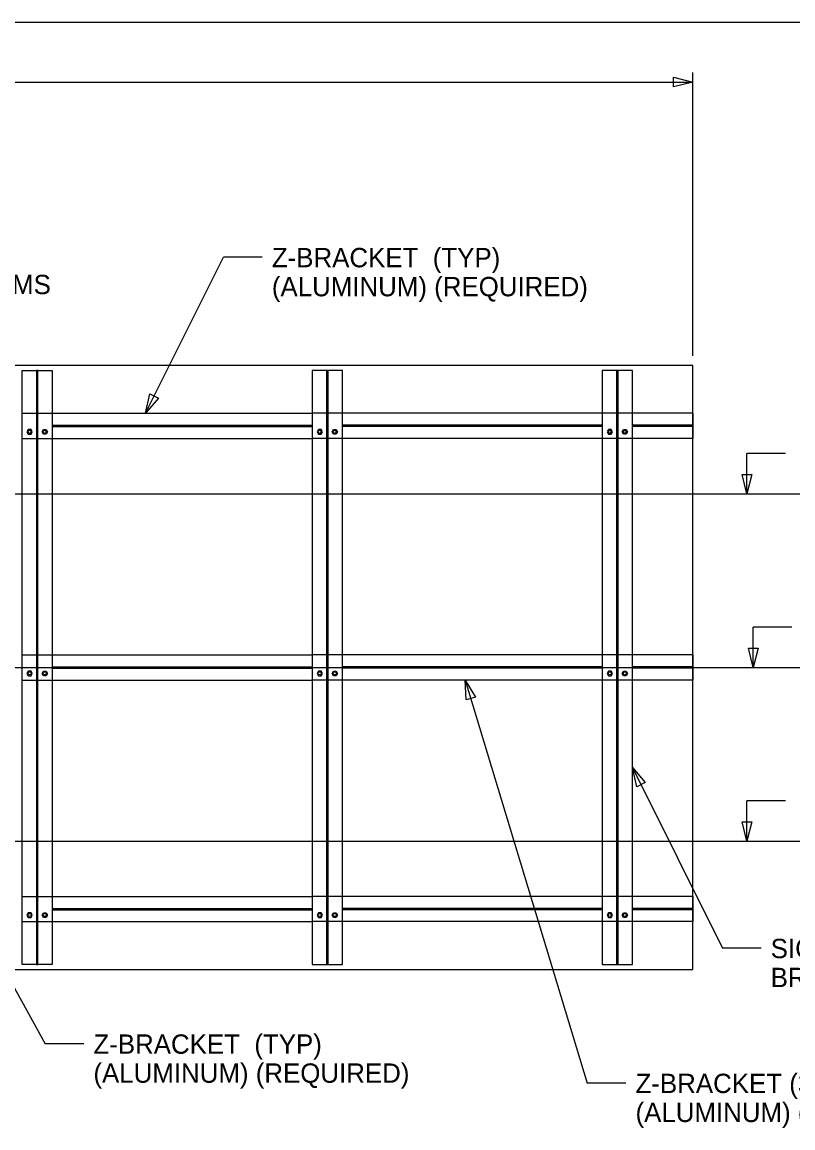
# Model space of a CAD drawing. Extents: x 3831399 to 3833095, y 499014 to 500202.
# Drawn here: x 3832677.7 to 3832797.3, y 499421.4 to 499593 of the extents above; entities that cross this region are included whole.
import ezdxf

# ---------------------------------------------------------------- set-up
doc = ezdxf.new("R2010")
doc.units = 0
for name, color, linetype in [('0-ANCHOR', 7, 'Continuous'), ('2', 7, 'Continuous'), ('CNTR', 7, 'Continuous'), ('DIM TXT', 7, 'Continuous'), ('sign', 7, 'Continuous'), ('structure', 7, 'Continuous')]:
    doc.layers.add(name, color=color, linetype=linetype)

msp = doc.modelspace()

# ---------------------------------------------------------------- linework, layer by layer
at = {"layer": '0-ANCHOR'}
for p, q in [((3832678.64, 499529.81), (3832678.43, 499529.45)), ((3832678.43, 499529.45), (3832678.64, 499529.09)), ((3832679.06, 499529.81), (3832678.64, 499529.81)), ((3832678.64, 499529.09), (3832679.06, 499529.09)), ((3832679.26, 499529.45), (3832679.06, 499529.81)), ((3832679.06, 499529.09), (3832679.26, 499529.45)), ((3832680.77, 499529.45), (3832680.98, 499529.81)), ((3832680.98, 499529.09), (3832680.77, 499529.45)), ((3832680.98, 499529.81), (3832681.39, 499529.81)), ((3832681.39, 499529.09), (3832680.98, 499529.09)), ((3832681.39, 499529.81), (3832681.6, 499529.45)), ((3832681.6, 499529.45), (3832681.39, 499529.09)), ((3832723.64, 499529.81), (3832723.43, 499529.45)), ((3832723.43, 499529.45), (3832723.64, 499529.09)), ((3832724.05, 499529.81), (3832723.64, 499529.81)), ((3832723.64, 499529.09), (3832724.05, 499529.09)), ((3832724.26, 499529.45), (3832724.05, 499529.81)), ((3832724.05, 499529.09), (3832724.26, 499529.45)), ((3832725.77, 499529.45), (3832725.98, 499529.81)), ((3832725.98, 499529.09), (3832725.77, 499529.45)), ((3832725.98, 499529.81), (3832726.39, 499529.81)), ((3832726.39, 499529.09), (3832725.98, 499529.09)), ((3832726.39, 499529.81), (3832726.6, 499529.45)), ((3832726.6, 499529.45), (3832726.39, 499529.09)), ((3832768.64, 499529.81), (3832768.43, 499529.45)), ((3832768.43, 499529.45), (3832768.64, 499529.09)), ((3832769.05, 499529.81), (3832768.64, 499529.81)), ((3832768.64, 499529.09), (3832769.05, 499529.09)), ((3832769.26, 499529.45), (3832769.05, 499529.81)), ((3832769.05, 499529.09), (3832769.26, 499529.45)), ((3832770.77, 499529.45), (3832770.97, 499529.81)), ((3832770.97, 499529.09), (3832770.77, 499529.45)), ((3832770.97, 499529.81), (3832771.39, 499529.81)), ((3832771.39, 499529.09), (3832770.97, 499529.09)), ((3832771.39, 499529.81), (3832771.6, 499529.45)), ((3832771.6, 499529.45), (3832771.39, 499529.09)), ((3832678.64, 499492.31), (3832678.43, 499491.95)), ((3832678.43, 499491.95), (3832678.64, 499491.59)), ((3832679.06, 499492.31), (3832678.64, 499492.31)), ((3832678.64, 499491.59), (3832679.06, 499491.59)), ((3832679.26, 499491.95), (3832679.06, 499492.31)), ((3832679.06, 499491.59), (3832679.26, 499491.95)), ((3832680.77, 499491.95), (3832680.98, 499492.31)), ((3832680.98, 499491.59), (3832680.77, 499491.95)), ((3832680.98, 499492.31), (3832681.39, 499492.31)), ((3832681.39, 499491.59), (3832680.98, 499491.59)), ((3832681.39, 499492.31), (3832681.6, 499491.95)), ((3832681.6, 499491.95), (3832681.39, 499491.59)), ((3832723.64, 499492.31), (3832723.43, 499491.95)), ((3832723.43, 499491.95), (3832723.64, 499491.59)), ((3832724.05, 499492.31), (3832723.64, 499492.31)), ((3832723.64, 499491.59), (3832724.05, 499491.59)), ((3832724.26, 499491.95), (3832724.05, 499492.31)), ((3832724.05, 499491.59), (3832724.26, 499491.95)), ((3832725.77, 499491.95), (3832725.98, 499492.31)), ((3832725.98, 499491.59), (3832725.77, 499491.95)), ((3832725.98, 499492.31), (3832726.39, 499492.31)), ((3832726.39, 499491.59), (3832725.98, 499491.59)), ((3832726.39, 499492.31), (3832726.6, 499491.95)), ((3832726.6, 499491.95), (3832726.39, 499491.59)), ((3832768.64, 499492.31), (3832768.43, 499491.95)), ((3832768.43, 499491.95), (3832768.64, 499491.59)), ((3832769.05, 499492.31), (3832768.64, 499492.31)), ((3832768.64, 499491.59), (3832769.05, 499491.59)), ((3832769.26, 499491.95), (3832769.05, 499492.31)), ((3832769.05, 499491.59), (3832769.26, 499491.95)), ((3832770.77, 499491.95), (3832770.97, 499492.31)), ((3832770.97, 499491.59), (3832770.77, 499491.95)), ((3832770.97, 499492.31), (3832771.39, 499492.31)), ((3832771.39, 499491.59), (3832770.97, 499491.59)), ((3832771.39, 499492.31), (3832771.6, 499491.95)), ((3832771.6, 499491.95), (3832771.39, 499491.59)), ((3832678.64, 499454.81), (3832678.43, 499454.45)), ((3832678.43, 499454.45), (3832678.64, 499454.09)), ((3832679.06, 499454.81), (3832678.64, 499454.81)), ((3832678.64, 499454.09), (3832679.06, 499454.09)), ((3832679.26, 499454.45), (3832679.06, 499454.81)), ((3832679.06, 499454.09), (3832679.26, 499454.45)), ((3832680.77, 499454.45), (3832680.98, 499454.81)), ((3832680.98, 499454.09), (3832680.77, 499454.45)), ((3832680.98, 499454.81), (3832681.39, 499454.81)), ((3832681.39, 499454.09), (3832680.98, 499454.09)), ((3832681.39, 499454.81), (3832681.6, 499454.45)), ((3832681.6, 499454.45), (3832681.39, 499454.09)), ((3832723.64, 499454.81), (3832723.43, 499454.45)), ((3832723.43, 499454.45), (3832723.64, 499454.09)), ((3832724.05, 499454.81), (3832723.64, 499454.81)), ((3832723.64, 499454.09), (3832724.05, 499454.09)), ((3832724.26, 499454.45), (3832724.05, 499454.81)), ((3832724.05, 499454.09), (3832724.26, 499454.45)), ((3832725.77, 499454.45), (3832725.98, 499454.81)), ((3832725.98, 499454.09), (3832725.77, 499454.45)), ((3832725.98, 499454.81), (3832726.39, 499454.81)), ((3832726.39, 499454.09), (3832725.98, 499454.09)), ((3832726.39, 499454.81), (3832726.6, 499454.45)), ((3832726.6, 499454.45), (3832726.39, 499454.09)), ((3832768.64, 499454.81), (3832768.43, 499454.45)), ((3832768.43, 499454.45), (3832768.64, 499454.09)), ((3832769.05, 499454.81), (3832768.64, 499454.81)), ((3832768.64, 499454.09), (3832769.05, 499454.09)), ((3832769.26, 499454.45), (3832769.05, 499454.81)), ((3832769.05, 499454.09), (3832769.26, 499454.45)), ((3832770.77, 499454.45), (3832770.97, 499454.81)), ((3832770.97, 499454.09), (3832770.77, 499454.45)), ((3832770.97, 499454.81), (3832771.39, 499454.81)), ((3832771.39, 499454.09), (3832770.97, 499454.09)), ((3832771.39, 499454.81), (3832771.6, 499454.45)), ((3832771.6, 499454.45), (3832771.39, 499454.09))]:
    msp.add_line(p, q, dxfattribs=at)
for centre in [(3832678.85, 499529.45), (3832681.18, 499529.45), (3832723.85, 499529.45), (3832726.18, 499529.45), (3832768.85, 499529.45), (3832771.18, 499529.45), (3832678.85, 499491.95), (3832681.18, 499491.95), (3832723.85, 499491.95), (3832726.18, 499491.95), (3832768.85, 499491.95), (3832771.18, 499491.95), (3832678.85, 499454.45), (3832681.18, 499454.45), (3832723.85, 499454.45), (3832726.18, 499454.45), (3832768.85, 499454.45), (3832771.18, 499454.45)]:
    msp.add_circle(centre, 0.244, dxfattribs=at)
at = {"layer": '2'}
msp.add_line((3832280.16, 499593.03), (3833066.16, 499593.03), dxfattribs=at)
at = {"layer": 'CNTR'}
for p, q in [((3832528.61, 499519.83), (3832815.35, 499519.83)), ((3832528.61, 499492.88), (3832829.18, 499492.88)), ((3832528.61, 499465.92), (3832815.12, 499465.92))]:
    msp.add_line(p, q, dxfattribs=at)
at = {"layer": 'DIM TXT'}
for p, q in [((3832533.3, 499583.72), (3832781.73, 499583.72)), ((3832781.73, 499541.25), (3832781.73, 499585.22)), ((3832696.82, 499532.33), (3832708.92, 499556.54)), ((3832714.92, 499556.54), (3832708.92, 499556.54)), ((3832790.12, 499519.83), (3832790.12, 499526.08)), ((3832796.12, 499526.08), (3832790.12, 499526.08)), ((3832791.1, 499492.88), (3832791.1, 499499.13)), ((3832797.1, 499499.13), (3832791.1, 499499.13)), ((3832746.43, 499490.92), (3832765.34, 499428.38)), ((3832772.35, 499477.37), (3832786.31, 499449.32)), ((3832790.12, 499465.92), (3832790.12, 499472.17)), ((3832796.12, 499472.17), (3832790.12, 499472.17)), ((3832670.7, 499453.43), (3832681.24, 499434.48)), ((3832792.31, 499449.32), (3832786.31, 499449.32)), ((3832687.24, 499434.48), (3832681.24, 499434.48)), ((3832771.34, 499428.38), (3832765.34, 499428.38))]:
    msp.add_line(p, q, dxfattribs=at)
for points in [[(3832778.73, 499584.47), (3832781.73, 499583.72), (3832778.73, 499582.97)], [(3832698.83, 499534.68), (3832696.82, 499532.33), (3832697.49, 499535.35)], [(3832790.87, 499522.83), (3832790.12, 499519.83), (3832789.37, 499522.83)], [(3832791.85, 499495.88), (3832791.1, 499492.88), (3832790.35, 499495.88)], [(3832746.58, 499487.84), (3832746.43, 499490.92), (3832748.01, 499488.27)], [(3832773.02, 499474.35), (3832772.35, 499477.37), (3832774.36, 499475.01)], [(3832790.87, 499468.92), (3832790.12, 499465.92), (3832789.37, 499468.92)]]:
    msp.add_lwpolyline(points, close=True, dxfattribs=at)
at = {"layer": 'sign'}
for p, q in [((3832781.73, 499539.75), (3832533.3, 499539.75)), ((3832781.73, 499446), (3832781.73, 499539.75)), ((3832677.68, 499532.33), (3832682.36, 499532.33)), ((3832682.36, 499532.33), (3832722.68, 499532.33)), ((3832727.36, 499532.33), (3832722.68, 499532.33)), ((3832767.67, 499532.33), (3832727.36, 499532.33)), ((3832772.35, 499532.33), (3832767.67, 499532.33)), ((3832781.73, 499532.33), (3832772.35, 499532.33)), ((3832781.73, 499532.33), (3832781.73, 499528.42)), ((3832682.36, 499530.47), (3832722.68, 499530.47)), ((3832767.67, 499530.47), (3832727.36, 499530.47)), ((3832781.73, 499530.47), (3832772.35, 499530.47)), ((3832682.36, 499530.28), (3832722.68, 499530.28)), ((3832767.67, 499530.28), (3832727.36, 499530.28)), ((3832781.73, 499530.28), (3832772.35, 499530.28)), ((3832677.68, 499528.42), (3832682.36, 499528.42)), ((3832682.36, 499528.42), (3832722.68, 499528.42)), ((3832727.36, 499528.42), (3832722.68, 499528.42)), ((3832767.67, 499528.42), (3832727.36, 499528.42)), ((3832772.35, 499528.42), (3832767.67, 499528.42)), ((3832781.73, 499528.42), (3832772.35, 499528.42)), ((3832677.68, 499494.83), (3832682.36, 499494.83)), ((3832682.36, 499494.83), (3832722.68, 499494.83)), ((3832727.36, 499494.83), (3832722.68, 499494.83)), ((3832767.67, 499494.83), (3832727.36, 499494.83)), ((3832772.35, 499494.83), (3832767.67, 499494.83)), ((3832781.73, 499494.83), (3832772.35, 499494.83)), ((3832781.73, 499494.83), (3832781.73, 499490.92)), ((3832682.36, 499492.97), (3832722.68, 499492.97)), ((3832682.36, 499492.78), (3832722.68, 499492.78)), ((3832767.67, 499492.97), (3832727.36, 499492.97)), ((3832767.67, 499492.78), (3832727.36, 499492.78)), ((3832781.73, 499492.97), (3832772.35, 499492.97)), ((3832781.73, 499492.78), (3832772.35, 499492.78)), ((3832677.68, 499490.92), (3832682.36, 499490.92)), ((3832682.36, 499490.92), (3832722.68, 499490.92)), ((3832727.36, 499490.92), (3832722.68, 499490.92)), ((3832767.67, 499490.92), (3832727.36, 499490.92)), ((3832772.35, 499490.92), (3832767.67, 499490.92)), ((3832781.73, 499490.92), (3832772.35, 499490.92)), ((3832677.68, 499457.33), (3832682.36, 499457.33)), ((3832682.36, 499457.33), (3832722.68, 499457.33)), ((3832727.36, 499457.33), (3832722.68, 499457.33)), ((3832767.67, 499457.33), (3832727.36, 499457.33)), ((3832772.35, 499457.33), (3832767.67, 499457.33)), ((3832781.73, 499457.33), (3832772.35, 499457.33)), ((3832781.73, 499457.33), (3832781.73, 499453.43)), ((3832682.36, 499455.48), (3832722.68, 499455.48)), ((3832682.36, 499455.28), (3832722.68, 499455.28)), ((3832767.67, 499455.48), (3832727.36, 499455.48)), ((3832767.67, 499455.28), (3832727.36, 499455.28)), ((3832781.73, 499455.48), (3832772.35, 499455.48)), ((3832781.73, 499455.28), (3832772.35, 499455.28)), ((3832677.68, 499453.43), (3832682.36, 499453.43)), ((3832682.36, 499453.43), (3832722.68, 499453.43)), ((3832727.36, 499453.43), (3832722.68, 499453.43)), ((3832767.67, 499453.43), (3832727.36, 499453.43)), ((3832772.35, 499453.43), (3832767.67, 499453.43)), ((3832781.73, 499453.43), (3832772.35, 499453.43)), ((3832533.3, 499446), (3832781.73, 499446))]:
    msp.add_line(p, q, dxfattribs=at)
at = {"layer": 'structure'}
for p, q in [((3832677.68, 499538.97), (3832682.36, 499538.97)), ((3832677.68, 499446.78), (3832677.68, 499538.97)), ((3832680.11, 499538.97), (3832679.93, 499538.97)), ((3832679.93, 499538.97), (3832679.93, 499446.78)), ((3832680.11, 499446.78), (3832680.11, 499538.97)), ((3832682.36, 499538.97), (3832682.36, 499446.78)), ((3832727.36, 499538.97), (3832722.68, 499538.97)), ((3832722.68, 499538.97), (3832722.68, 499446.78)), ((3832724.93, 499538.97), (3832725.11, 499538.97)), ((3832724.93, 499446.78), (3832724.93, 499538.97)), ((3832725.11, 499538.97), (3832725.11, 499446.78)), ((3832727.36, 499446.78), (3832727.36, 499538.97)), ((3832772.35, 499538.97), (3832767.67, 499538.97)), ((3832767.67, 499538.97), (3832767.67, 499446.78)), ((3832769.92, 499538.97), (3832770.1, 499538.97)), ((3832769.92, 499446.78), (3832769.92, 499538.97)), ((3832770.1, 499538.97), (3832770.1, 499446.78)), ((3832772.35, 499446.78), (3832772.35, 499538.97)), ((3832682.36, 499446.78), (3832677.68, 499446.78)), ((3832679.93, 499446.78), (3832680.11, 499446.78)), ((3832722.68, 499446.78), (3832727.36, 499446.78)), ((3832725.11, 499446.78), (3832724.93, 499446.78)), ((3832767.67, 499446.78), (3832772.35, 499446.78)), ((3832770.1, 499446.78), (3832769.92, 499446.78))]:
    msp.add_line(p, q, dxfattribs=at)

# ---------------------------------------------------------------- texts
at = {"layer": 'DIM TXT'}
for s, height, p in [('Z-BRACKET  (TYP)', 2.9999, (3832716.42, 499554.98)), ('  DMS', 3, (3832670.99, 499550.81)), ('(ALUMINUM) (REQUIRED)', 2.9999, (3832716.42, 499550.48)), ('SIGN SUPPORT ', 2.9999, (3832793.81, 499447.76)), ('BRACKET (TYP.)', 2.9999, (3832793.81, 499443.26)), ('Z-BRACKET  (TYP)', 2.9999, (3832688.74, 499432.92)), ('(ALUMINUM) (REQUIRED)', 2.9999, (3832688.74, 499428.42)), ('Z-BRACKET (3RD) (TYP)', 2.9999, (3832772.84, 499426.82)), ('(ALUMINUM) (SEE NOTE 7)', 2.9999, (3832772.84, 499422.32))]:
    msp.add_text(s, height=height, dxfattribs=at).set_placement(p)

doc.saveas('drawing.dxf')
